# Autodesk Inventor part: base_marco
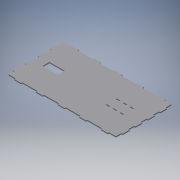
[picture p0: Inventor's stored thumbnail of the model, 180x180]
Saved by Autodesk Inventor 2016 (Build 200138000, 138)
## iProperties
Created: 2017-06
Part Number: base_marco
Material: Generic
Document SubType Name: Modeling
Designer: laboratorioesan
Density: 1 g/cm^3
Appearance: Default
Author: laboratorioesan
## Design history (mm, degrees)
sketch "Sketch1"
  geometry: L1 (312.5, 0)-(412.5, 0) reference; L2 (312.5, 0)-(312.5, -18.5) reference; L3 (412.5, -18.5)-(312.5, -18.5) reference; L4 (412.5, 0)-(412.5, -18.5) reference; L5 (0, 0)-(100, 0) reference; L6 (0, 0)-(0, -18.5) reference; L7 (100, -18.5)-(0, -18.5) reference; L8 (100, 0)-(100, -18.5) reference; L9 (512.5, 80)-(512.5, 180) reference; L10 (512.5, 80)-(531, 80) reference; L11 (531, 180)-(531, 80) reference; L12 (512.5, 180)-(531, 180) reference; L13 (512.5, 620)-(512.5, 720) reference; L14 (512.5, 620)-(531, 620) reference; L15 (531, 720)-(531, 620) reference; L16 (512.5, 720)-(531, 720) reference; L17 (512.5, 440)-(512.5, 540) reference; L18 (512.5, 440)-(531, 440) reference; L19 (531, 540)-(531, 440) reference; L20 (512.5, 540)-(531, 540) reference; L21 (512.5, 260)-(512.5, 360) reference; L22 (512.5, 260)-(531, 260) reference; L23 (531, 360)-(531, 260) reference; L24 (512.5, 360)-(531, 360) reference; L25 (312.5, 818.5)-(412.5, 818.5) reference; L26 (312.5, 818.5)-(312.5, 800) reference; L27 (412.5, 800)-(312.5, 800) reference; L28 (412.5, 818.5)-(412.5, 800) reference; L29 (0, 818.5)-(100, 818.5) reference; L30 (0, 818.5)-(0, 800) reference; L31 (100, 800)-(0, 800) reference; L32 (100, 818.5)-(100, 800) reference; L33 (-312.5, 818.5)-(-212.5, 818.5) reference; L34 (-312.5, 818.5)-(-312.5, 800) reference; L35 (-212.5, 800)-(-312.5, 800) reference; L36 (-212.5, 818.5)-(-212.5, 800) reference; L37 (-625, 818.5)-(-525, 818.5) reference; L38 (-625, 818.5)-(-625, 800) reference; L39 (-525, 800)-(-625, 800) reference; L40 (-525, 818.5)-(-525, 800) reference; L41 (-937.5, 818.5)-(-837.5, 818.5) reference; L42 (-937.5, 818.5)-(-937.5, 800) reference; L43 (-837.5, 800)-(-937.5, 800) reference; L44 (-837.5, 818.5)-(-837.5, 800) reference; L45 (-1037.5, 720)-(-1037.5, 620) reference; L46 (-1037.5, 720)-(-1056, 720) reference; L47 (-1056, 620)-(-1056, 720) reference; L48 (-1037.5, 620)-(-1056, 620) reference; L49 (-1037.5, 540)-(-1037.5, 440) reference; L50 (-1037.5, 540)-(-1056, 540) reference; L51 (-1056, 440)-(-1056, 540) reference; L52 (-1037.5, 440)-(-1056, 440) reference; L53 (-1037.5, 360)-(-1037.5, 260) reference; L54 (-1037.5, 360)-(-1056, 360) reference; L55 (-1056, 260)-(-1056, 360) reference; L56 (-1037.5, 260)-(-1056, 260) reference; L57 (-1037.5, 180)-(-1037.5, 80) reference; L58 (-1037.5, 180)-(-1056, 180) reference; L59 (-1056, 80)-(-1056, 180) reference; L60 (-1037.5, 80)-(-1056, 80) reference; L61 (-937.5, 0)-(-837.5, 0) reference; L62 (-937.5, 0)-(-937.5, -18.5) reference; L63 (-837.5, -18.5)-(-937.5, -18.5) reference; L64 (-837.5, 0)-(-837.5, -18.5) reference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; 2 further points; 1 other entity
  constraints: 152 end point, 38 parallel, 19 horizontal, 19 perpendicular, 18 point on line, 1 other
  dimensions: "d0" = 18 distance of L81.end L80.end; "d1" = 18 distance of L85.end L84.end; "d2" = 18 distance of L89.end L88.end; "d3" = 18 distance of L93.end L92.end; "d4" = 18 distance of L97.end L96.end; "d5" = 18 distance of L101.end L102.end; "d6" = 18 distance of L105.end L106.end; "d7" = 18 distance of L109.end L110.end; "d8" = 18 distance of L113.end L114.end; "d9" = 18 distance of L117.end L116.end; "d10" = 18 distance of L121.end L120.end; "d11" = 18 distance of L125.end L124.end; "d12" = 18 distance of L128.end L129.end; "d13" = 18 distance of L133.end L132.end; "d14" = 18 distance of L137.end L138.end; "d15" = 18 distance of L141.end L142.end; "d16" = 18 distance of L145.end L146.end; "d17" = 18 distance of L149.end L150.end
extrude "Extrusion1" new body sketch "Sketch1" distance "d18" = 15.5; taper "d19" = 0 deg
extrude "Extrusion2" cut sketch "Sketch2" distance "d29" = 15.5; taper "d30" = 0 deg
sketch "Sketch3"
  geometry: L1 (45.342, 320)-(45.342, 335.5) reference; L2 (45.342, 335.5)-(95.342, 335.5) reference; L3 (95.342, 335.5)-(95.342, 320) reference; L4 (95.342, 320)-(45.342, 320) reference; L5 (195.342, 480)-(195.342, 464.5) reference; L6 (195.342, 464.5)-(145.342, 464.5) reference; L7 (145.342, 464.5)-(145.342, 480) reference; L8 (145.342, 480)-(195.342, 480) reference; L9 (145.342, 335.5)-(195.342, 335.5) reference; L10 (195.342, 335.5)-(195.342, 320) reference; L11 (195.342, 320)-(145.342, 320) reference; L12 (145.342, 320)-(145.342, 335.5) reference; L13 (95.342, 480)-(95.342, 464.5) reference; L14 (95.342, 464.5)-(45.342, 464.5) reference; L15 (45.342, 464.5)-(45.342, 480) reference; L16 (45.342, 480)-(95.342, 480) reference; L17 (295.348, 480)-(295.348, 464.5) reference; L18 (295.348, 464.5)-(245.348, 464.5) reference; L19 (245.348, 464.5)-(245.348, 480) reference; L20 (245.348, 480)-(295.348, 480) reference; L21 (245.348, 320)-(245.348, 335.5) reference; L22 (245.348, 335.5)-(295.348, 335.5) reference; L23 (295.348, 335.5)-(295.348, 320) reference; L24 (295.348, 320)-(245.348, 320) reference; L25 (512.5, 0)-(512.5, 80) reference; L26 (512.5, 80)-(530.5, 80) reference; L27 (530.5, 80)-(530.5, 180) reference; L28 (530.5, 180)-(512.5, 180) reference; L29 (512.5, 180)-(512.5, 260) reference; L30 (512.5, 260)-(530.5, 260) reference; L31 (530.5, 260)-(530.5, 360) reference; L32 (530.5, 360)-(512.5, 360) reference; L33 (512.5, 360)-(512.5, 440) reference; L34 (512.5, 440)-(530.5, 440) reference; L35 (530.5, 440)-(530.5, 540) reference; L36 (530.5, 540)-(512.5, 540) reference; L37 (512.5, 540)-(512.5, 620) reference; L38 (512.5, 620)-(530.5, 620) reference; L39 (530.5, 620)-(530.5, 720) reference; L40 (530.5, 720)-(512.5, 720) reference; L41 (512.5, 720)-(512.5, 800) reference; L42 (512.5, 800)-(412.5, 800) reference; L43 (412.5, 800)-(412.5, 818) reference; L44 (412.5, 818)-(312.5, 818) reference; L45 (312.5, 818)-(312.5, 800) reference; L46 (312.5, 800)-(100, 800) reference; L47 (100, 800)-(100, 818) reference; L48 (100, 818)-(0, 818) reference; L49 (0, 818)-(0, 800) reference; L50 (0, 800)-(-212.5, 800) reference; L51 (-212.5, 800)-(-212.5, 818) reference; L52 (-212.5, 818)-(-312.5, 818) reference; L53 (-312.5, 818)-(-312.5, 800) reference; L54 (-312.5, 800)-(-525, 800) reference; L55 (-525, 800)-(-525, 818) reference; L56 (-525, 818)-(-625, 818) reference; L57 (-625, 818)-(-625, 800) reference; L58 (-625, 800)-(-837.5, 800) reference; L59 (-837.5, 800)-(-837.5, 818) reference; L60 (-837.5, 818)-(-937.5, 818) reference; L61 (-937.5, 818)-(-937.5, 800) reference; L62 (-937.5, 800)-(-1037.5, 800) reference; L63 (-1037.5, 800)-(-1037.5, 720) reference; L64 (-1037.5, 720)-(-1055.5, 720) reference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; 5 further points
  constraints: 10 end point, 6 midpoint, 2 parallel, 1 horizontal, 1 horizontal alignment, 1 perpendicular, 1 vertical alignment
  dimensions: "d31" = 220 distance of L106.end L107.end; "d32" = 100 distance of L105.end L106.end
extrude "Extrusion3" cut sketch "Sketch3" distance "d34" = 18.5; taper "d35" = 0 deg
body "Solid1"
node "Reference1"
node "Reference2"
node "Reference3"
node "Reference4"
node "Reference5"
node "Reference6"
node "Reference7"
node "Reference8"
node "Reference9"
node "Reference10"
node "Reference11"
node "Reference12"
node "Reference13"
node "Reference14"
node "Reference15"
node "Reference16"
node "Reference17"
node "Reference18"
node "Reference19"
node "Reference20"
node "Reference21"
node "Reference22"
node "Projected Loop2"
node "Reference29"
node "Reference30"
node "Reference31"
other parameters: "d24" = 15.5
